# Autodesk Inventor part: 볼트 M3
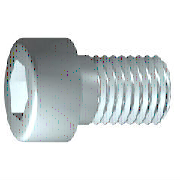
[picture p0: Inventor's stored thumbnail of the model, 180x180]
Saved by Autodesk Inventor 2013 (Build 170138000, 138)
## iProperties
IsCustomPart: 0
Created: 2012-02
Part Number: 볼트 M3
Material: 스테인리스강
Description: 6각 소켓 머리 캡 나사
Document SubType Name: Modeling
Standard: ISO 4762
Designer: mduedu
Standard Revision: Fourth edition 2004-03-01
Standards Organization: ISO
Language: ko-KR
Size Designation: M3 x 8
Categories: <MemberInstance><Categories><Category DisplayName="조임쇠" InternalName="e4da775c-781d-43d5-af7c-5136215cf5a6" Mnemonic="FSTN"><Category DisplayName="볼트" InternalN
Density: 7.75 g/cm^3
Author: mduedu
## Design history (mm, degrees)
sketch "스케치1"
  geometry: L1 (-0.867, 0)-(8, 0); L2 (8, 0)-(8, 1.5); L3 (8, 1.5)-(1.25, 1.5); L4 (1.25, 1.5)-(0.943, 1.5); L5 (0.943, 1.5)-(0, 1.5); L6 (0, 1.5)-(0, 2.75); L7 (0, 2.75)-(-3, 2.75); L8 (-3, 2.75)-(-3, 1.443); L9 (-3, 1.443)-(-1.7, 1.443); L10 (-1.7, 1.443)-(-0.867, 0); L11 (-5.2, 0)-(10.2, 0) reference; L12 (0, -0.55)-(0, 3.3) reference; L13 (1.25, 1.5)-(0, 1.5)
  constraints: 22 end point, 6 parallel, 2 collinear, 2 perpendicular, 1 horizontal, 1 point on line
  dimensions: "d1" = 6.75 distance from line of L3.end L2 (= GEL); "d2" = 0.30683 distance of L4.end L3.end (computed from GAL); "d3" = 3 distance between parallel lines of L8 L6 (= KOH); "d4" = 1.3 distance of L8.end L9.end (= INTI); "d5" = 60 deg angle of L10 L1; "d6" = 3 diameter of L3 L1 (= GD); "d7" = 3 diameter of L5 L1 (= BDM); "d8" = 2.88675 diameter of L9 L1 (= 1.1547 x SW); "d9" = 5.5 diameter of L7 L1 (= KOD); "d26" = 8 distance between parallel lines of L12 L2 (= NLG)
revolve "본체" sketch "스케치1" stored, may be unused: angle "d10" = 90 deg
sketch "스케치2"
  geometry: L1 (0, -3.85)-(0, 3.85) reference; L2 (-3.85, 0)-(3.85, 0) reference; L3 (1.443, 0)-(0.722, -1.25); L4 (0.722, -1.25)-(-0.722, -1.25); L5 (-0.722, -1.25)-(-1.443, 0); L6 (-1.443, 0)-(-0.722, 1.25); L7 (-0.722, 1.25)-(0.722, 1.25); L8 (0.722, 1.25)-(1.443, 0); 2 further points
  constraints: 12 end point, 1 coincident, 1 horizontal alignment, 1 point on line, 12 other
extrude "슬롯" join sketch "스케치2" stored distance "d11" = 10; taper "d12" = 0 deg
workplane "Work Plane1"
fillet "Fillet2" dims "d30" = 0.1 (= R)
body "Solid1"
fillet "모깎기1" dims "d17" = 0.3 (= RR)
feature "스레드" dims "d13" = 6.75 (= GEL), "d14" = 0
chamfer "모따기1" distance "d15" = 0.30673 (= -0.5 x SPD + 0.5 x GD); stored, may be unused: second distance "d16" = 0.30673 (= GUL), angle "d27" = 45 deg
other parameters: "GD" = 3 [user parameter; used in 2 equation terms], "NLG" = 8 [user parameter; used in 1 equation term], "GEL" = 6.75 [user parameter; used in 2 equation terms], "KOD" = 5.5 [user parameter; used in 1 equation term], "KOH" = 3 [user parameter; used in 1 equation term], "INTI" = 1.3 [user parameter; used in 1 equation term], "GAL" = 0.30673 (= 0.61345 x PTC) [user parameter; used in 1 equation term], "GUL" = 0.30673 (= 0.61345 x PTC) [user parameter; used in 1 equation term], "BDM" = 3 (= NND) [user parameter; used in 1 equation term], "SW" = 2.5 [user parameter; used in 2 equation terms], "RR" = 0.3 [user parameter; used in 1 equation term], "SPD" = 2.38655 (= NND - 1.2269 x PTC) [user parameter; used in 1 equation term], "d19" = 0, "d28" = 0, "d29" = 0, "R" = 0.1 [user parameter; used in 1 equation term], "TOA" = 30 deg [user parameter], "GD1" = 2.38655 (= THREADDIA - 1.2269 x PTC) [user parameter], "THREADDIA" = 3 [user parameter; used in 1 equation term], "FAWI" = 45 deg [user parameter], "PTC" = 0.5 [user parameter; used in 5 equation terms], "NND" = 3 [user parameter; used in 2 equation terms], "E0" = 2.8875 (= 1.155 x SW) [user parameter]
